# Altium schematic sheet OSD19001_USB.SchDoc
size B; Organization: Altium Limited; DocumentNumber: 4; SheetNumber: 4; SheetTotal: 4; SchematicTitle: OSD32MP1 BREAKOUT MODULE (USB)
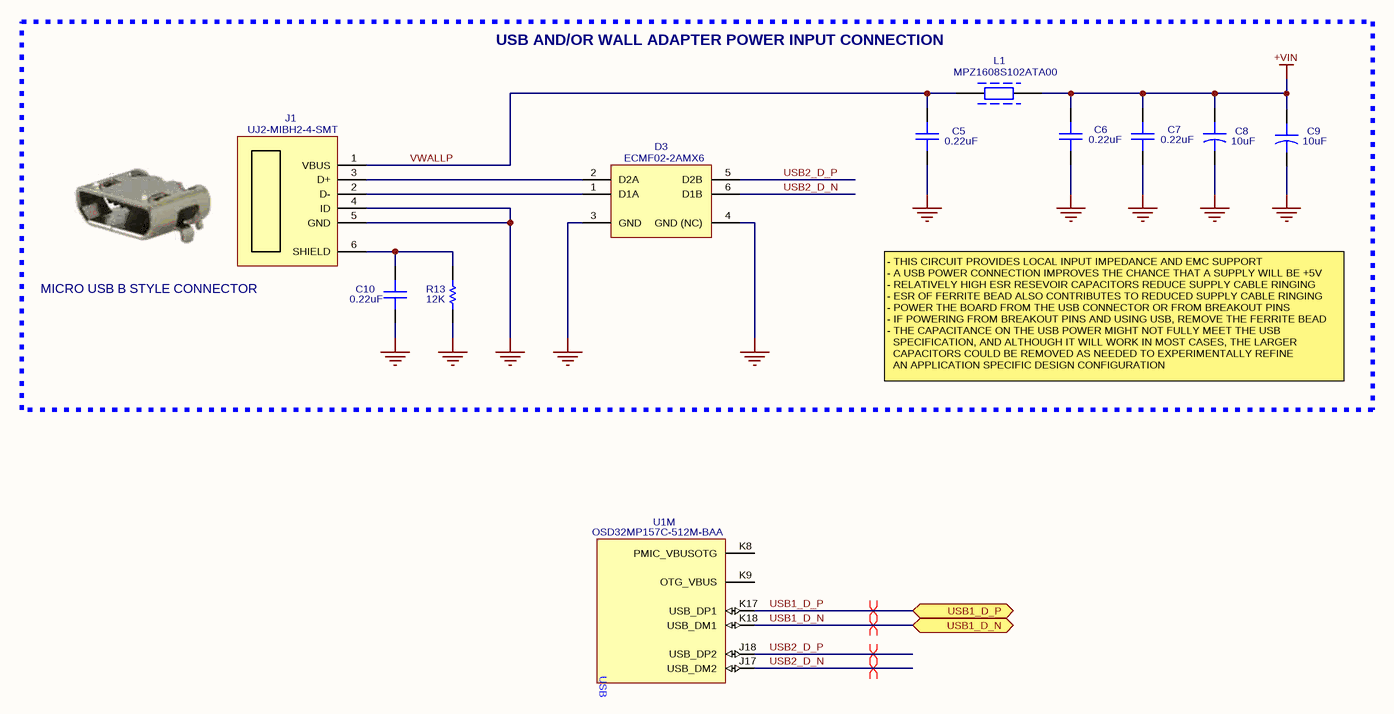
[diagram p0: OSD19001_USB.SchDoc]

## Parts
C5  0.22uF  [LP_0603_HIGH]
C6  0.22uF  [LP_0603_HIGH]
C7  0.22uF  [LP_0603_HIGH]
C8  10uF  [LP_EIAB]
C9  10uF  [LP_EIAB]
C10  0.22uF  [LP_0603_HIGH]
D3  ECMF02-2AMX6  [DFN6_6L_ST]
J1  UJ2-MIBH2-4-SMT  [CUI_UJ2-MIBH2-4-SMT]
L1  MPZ1608S102ATA00  [LP_0603_IND]
R13  12K  [LP_0603_LOW]
U1  OSD32MP157C-512M-BAA  [BGA_OCTAVO_SIP_OSD32MP157C]  (part M of 17)

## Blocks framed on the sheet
USB AND/OR WALL ADAPTER POWER INPUT CONNECTION: C5-C10 D3 J1 L1 R13

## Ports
USB1_D_N (bidir), USB1_D_P (bidir)

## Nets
+VIN: C6.2 C7.2 C8.1 C9.1 L1.2
GND: C5.1 C6.1 C7.1 C8.2 C9.2 C10.1 D3.3(GND) D3.4(GND_(NC)) J1.4(ID) J1.5(GND) R13.1
USB1_D_N: U1.K18(USB_DM1) ; port USB1_D_N
USB1_D_P: U1.K17(USB_DP1) ; port USB1_D_P
USB2_D_N: D3.6(D1B) U1.J17(USB_DM2)
USB2_D_P: D3.5(D2B) U1.J18(USB_DP2)
VWALLP: C5.2 J1.1(VBUS) L1.1
NetC10_2: C10.2 J1.6(SHIELD) R13.2
NetD3_1: D3.1(D1A) J1.2(D-)
NetD3_2: D3.2(D2A) J1.3(D+)

Not connected (* = marked no-connect by the designer): U1 K8(PMIC_VBUSOTG) K9(OTG_VBUS)

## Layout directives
differential pair: USB1_D_N, USB1_D_P, USB2_D_N, USB2_D_P

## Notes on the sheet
- MICRO USB B STYLE CONNECTOR
- - THIS CIRCUIT PROVIDES LOCAL INPUT IMPEDANCE AND EMC SUPPORT
  - A USB POWER CONNECTION IMPROVES THE CHANCE THAT A SUPPLY WILL BE +5V
  - RELATIVELY HIGH ESR RESEVOIR CAPACITORS REDUCE SUPPLY CABLE RINGING
  - ESR OF FERRITE BEAD ALSO CONTRIBUTES TO REDUCED SUPPLY CABLE RINGING
  - POWER THE BOARD FROM THE USB CONNECTOR OR FROM BREAKOUT PINS
  - IF POWERING FROM BREAKOUT PINS AND USING USB, REMOVE THE FERRITE BEAD
  - THE CAPACITANCE ON THE USB POWER MIGHT NOT FULLY MEET THE USB
  SPECIFICATION, AND ALTHOUGH IT WILL WORK IN MOST CASES, THE LARGER
  CAPACITORS COULD BE REMOVED AS NEEDED TO EXPERIMENTALLY REFINE
  AN APPLICATION SPECIFIC DESIGN CONFIGURATION

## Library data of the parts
C5-C7 C10 = CERCAP: Tolerance: 10%; Voltage: 25V
C8 C9 = POLCAP: Tolerance: 20%; Voltage: 10V
D3 = ECMF02-2AMX6: USB Filter And ESD Protection
J1 = USB_MICRO_B: USB Micro B Connetor
L1 = BEAD: Impedence: 300; CurrentRating: 0.8A
R13 = RESISTOR: Tolerance: 5%; Power: 0.1W; Voltage: 50V
U1 = OSD32MP157C: Octavo ST Processor SIP; Manufacturer: Octavo Systems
